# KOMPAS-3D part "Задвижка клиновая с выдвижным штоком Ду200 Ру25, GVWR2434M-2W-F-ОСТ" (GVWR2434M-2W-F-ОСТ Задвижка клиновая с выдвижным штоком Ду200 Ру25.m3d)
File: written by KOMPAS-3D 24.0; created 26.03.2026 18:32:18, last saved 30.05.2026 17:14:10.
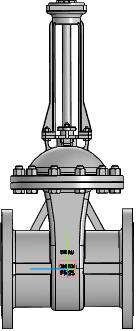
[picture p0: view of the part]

Document properties: Автор: R2D2; Полное имя файла: E:\Работа\Зайцев\GVWR2434M-2W-F-ОСТ Задвижка клиновая с выдвижным штоком DN.ru Ду50-300 Ру25\исходные материалы\DN200\DN200\GVWR2434M-2W-F-ОСТ Задвижка клиновая с выдвижным штоком Ду200 Ру25.m3d

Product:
- Part/product: Задвижка клиновая с выдвижным штоком Ду200 Ру25  | designation GVWR2434M-2W-F-ОСТ
    Масса: 100
    Раздел спецификации: Прочие изделия
    Примечание: D040-07590

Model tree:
1. Операция без истории:1

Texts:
  GVWR2434M-2W-F-ОСТ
